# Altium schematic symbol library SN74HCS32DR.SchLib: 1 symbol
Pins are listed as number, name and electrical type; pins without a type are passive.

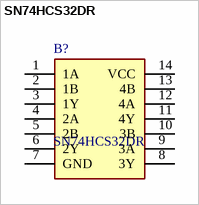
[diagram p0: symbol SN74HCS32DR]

## SN74HCS32DR
designator B?
Logic Gates Quadruple 2-input OR gates with Schmitt-trigger inputs 14-SOIC -40 to 125; Manufacturer_Name: Texas Instruments; Geometry.Height: 1.75mm
footprint SOIC127P600X175-14N
pins: 1 1A, 2 1B, 3 1Y, 4 2A, 5 2B, 6 2Y, 7 GND, 8 3Y, 9 3A, 10 3B, 11 4Y, 12 4A, 13 4B, 14 VCC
